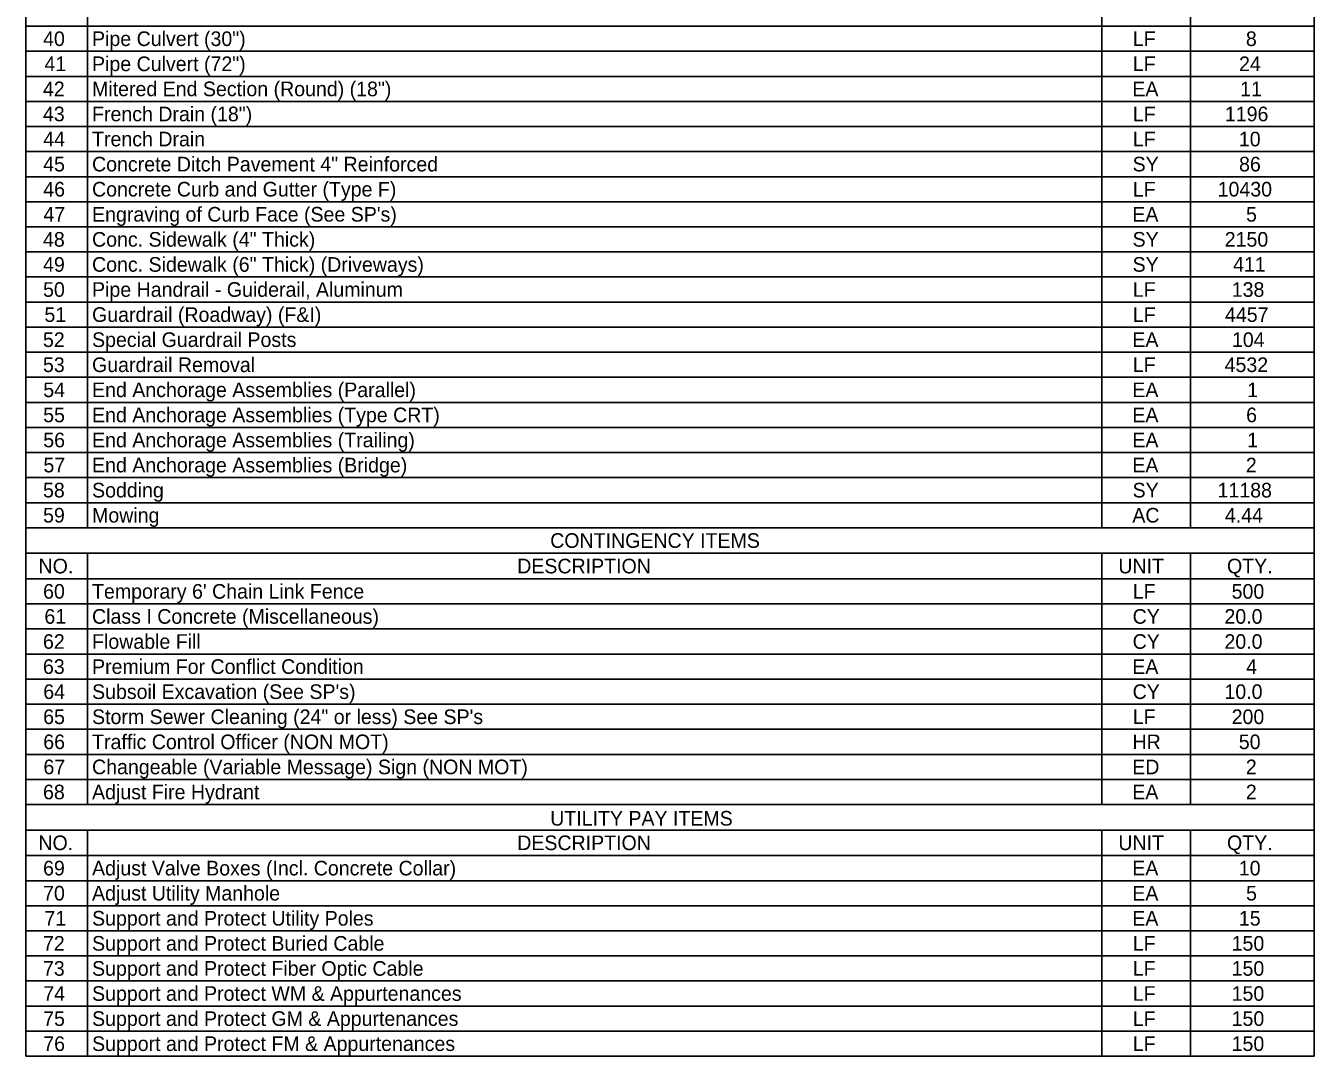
# Model space of a CAD drawing. Extents: x 0.3 to 14.6, y -0.2 to 9.6.
# Drawn here: x 0.29 to 6.07, y 0.33 to 4.95 of the extents above; entities that cross this region are included whole.
import ezdxf

# ---------------------------------------------------------------- set-up
doc = ezdxf.new("R2010")
doc.units = 0
for name, color, linetype in [('SumBoxBorder_dp', 7, 'Continuous'), ('SumBoxLines_dp', 7, 'Continuous'), ('TextLabel', 7, 'Continuous')]:
    doc.layers.add(name, color=color, linetype=linetype)

msp = doc.modelspace()

# ---------------------------------------------------------------- linework, layer by layer
at = {"layer": 'SumBoxBorder_dp'}
for p, q in [((0.2867, 9.5674), (0.2867, 0.3304)), ((6.0692, 9.5674), (6.0692, 0.3304)), ((0.2867, 2.7009), (6.0692, 2.7009)), ((0.2867, 2.5864), (6.0692, 2.5864)), ((0.2867, 2.5864), (6.0692, 2.5864)), ((0.2867, 1.4594), (6.0692, 1.4594)), ((0.2867, 1.3449), (6.0692, 1.3449)), ((0.2867, 1.3449), (6.0692, 1.3449)), ((0.2867, 0.3304), (6.0692, 0.3304))]:
    msp.add_line(p, q, dxfattribs=at)
at = {"layer": 'SumBoxLines_dp'}
for p, q in [((0.5642, 9.4529), (0.5642, 2.7009)), ((0.5642, 9.4529), (0.5642, 2.7009)), ((5.1167, 9.4529), (5.1167, 2.7009)), ((5.1167, 9.4529), (5.1167, 2.7009)), ((5.5142, 9.4529), (5.5142, 2.7009)), ((5.5142, 9.4529), (5.5142, 2.7009)), ((0.2867, 4.9509), (6.0692, 4.9509)), ((0.2867, 4.9509), (6.0692, 4.9509)), ((0.2867, 4.8384), (6.0692, 4.8384)), ((0.2867, 4.8384), (6.0692, 4.8384)), ((0.2867, 4.7259), (6.0692, 4.7259)), ((0.2867, 4.7259), (6.0692, 4.7259)), ((0.2867, 4.6134), (6.0692, 4.6134)), ((0.2867, 4.6134), (6.0692, 4.6134)), ((0.2867, 4.5009), (6.0692, 4.5009)), ((0.2867, 4.5009), (6.0692, 4.5009)), ((0.2867, 4.3884), (6.0692, 4.3884)), ((0.2867, 4.3884), (6.0692, 4.3884)), ((0.2867, 4.2759), (6.0692, 4.2759)), ((0.2867, 4.2759), (6.0692, 4.2759)), ((0.2867, 4.1634), (6.0692, 4.1634)), ((0.2867, 4.1634), (6.0692, 4.1634)), ((0.2867, 4.0509), (0.5642, 4.0509)), ((0.2867, 4.0509), (6.0692, 4.0509)), ((0.2867, 3.9384), (6.0692, 3.9384)), ((0.2867, 3.9384), (6.0692, 3.9384)), ((0.2867, 3.8259), (6.0692, 3.8259)), ((0.2867, 3.8259), (6.0692, 3.8259)), ((0.2867, 3.7134), (6.0692, 3.7134)), ((0.2867, 3.7134), (6.0692, 3.7134)), ((0.2867, 3.6009), (6.0692, 3.6009)), ((0.2867, 3.6009), (6.0692, 3.6009)), ((0.2867, 3.4884), (6.0692, 3.4884)), ((0.2867, 3.4884), (6.0692, 3.4884)), ((0.2867, 3.3759), (6.0692, 3.3759)), ((0.2867, 3.3759), (6.0692, 3.3759)), ((0.2867, 3.2634), (6.0692, 3.2634)), ((0.2867, 3.2634), (6.0692, 3.2634)), ((0.2867, 3.1509), (6.0692, 3.1509)), ((0.2867, 3.1509), (6.0692, 3.1509)), ((0.2867, 3.0384), (6.0692, 3.0384)), ((0.2867, 3.0384), (6.0692, 3.0384)), ((0.2867, 2.9259), (6.0692, 2.9259)), ((0.2867, 2.9259), (6.0692, 2.9259)), ((0.2867, 2.8134), (6.0692, 2.8134)), ((0.2867, 2.8134), (6.0692, 2.8134)), ((0.2867, 2.7009), (0.5642, 2.7009)), ((0.5642, 2.5864), (0.5642, 1.4594)), ((0.5642, 2.5864), (0.5642, 1.4594)), ((5.1167, 2.5864), (5.1167, 1.4594)), ((5.1167, 2.5864), (5.1167, 1.4594)), ((5.5142, 2.5864), (5.5142, 1.4594)), ((5.5142, 2.5864), (5.5142, 1.4594)), ((0.2867, 2.4719), (6.0692, 2.4719)), ((0.2867, 2.4719), (6.0692, 2.4719)), ((0.2867, 2.3594), (6.0692, 2.3594)), ((0.2867, 2.3594), (6.0692, 2.3594)), ((0.2867, 2.2469), (6.0692, 2.2469)), ((0.2867, 2.2469), (6.0692, 2.2469)), ((0.2867, 2.1344), (6.0692, 2.1344)), ((0.2867, 2.1344), (6.0692, 2.1344)), ((0.2867, 2.0219), (6.0692, 2.0219)), ((0.2867, 2.0219), (6.0692, 2.0219)), ((0.2867, 1.9094), (6.0692, 1.9094)), ((0.2867, 1.9094), (6.0692, 1.9094)), ((0.2867, 1.7969), (6.0692, 1.7969)), ((0.2867, 1.7969), (6.0692, 1.7969)), ((0.2867, 1.6844), (6.0692, 1.6844)), ((0.2867, 1.6844), (6.0692, 1.6844)), ((0.2867, 1.5719), (6.0692, 1.5719)), ((0.2867, 1.5719), (6.0692, 1.5719)), ((0.2867, 1.4594), (6.0692, 1.4594)), ((0.5642, 1.3449), (0.5642, 0.3304)), ((0.5642, 1.3449), (0.5642, 0.3304)), ((5.1167, 1.3449), (5.1167, 0.3304)), ((5.1167, 1.3449), (5.1167, 0.3304)), ((5.5142, 1.3449), (5.5142, 0.3304)), ((5.5142, 1.3449), (5.5142, 0.3304)), ((0.2867, 1.2304), (6.0692, 1.2304)), ((0.2867, 1.2304), (6.0692, 1.2304)), ((0.2867, 1.1179), (6.0692, 1.1179)), ((0.2867, 1.1179), (6.0692, 1.1179)), ((0.2867, 1.0054), (6.0692, 1.0054)), ((0.2867, 1.0054), (6.0692, 1.0054)), ((0.2867, 0.8929), (6.0692, 0.8929)), ((0.2867, 0.8929), (6.0692, 0.8929)), ((0.2867, 0.7804), (6.0692, 0.7804)), ((0.2867, 0.7804), (6.0692, 0.7804)), ((0.2867, 0.6679), (6.0692, 0.6679)), ((0.2867, 0.6679), (6.0692, 0.6679)), ((0.2867, 0.5554), (6.0692, 0.5554)), ((0.2867, 0.5554), (6.0692, 0.5554)), ((0.2867, 0.4429), (6.0692, 0.4429)), ((0.2867, 0.4429), (6.0692, 0.4429))]:
    msp.add_line(p, q, dxfattribs=at)

# ---------------------------------------------------------------- texts
at = {"layer": 'TextLabel'}
for s, height, p in [('40', 0.06563, (0.3644, 4.8619)), ('Pipe Culvert (30")', 0.065625, (0.5842, 4.8619)), ('LF', 0.06563, (5.255, 4.8619)), ('8', 0.0656, (5.7625, 4.8619)), ('41', 0.06563, (0.3704, 4.7494)), ('Pipe Culvert (72")', 0.065625, (0.5842, 4.7494)), ('LF', 0.06563, (5.255, 4.7494)), ('24', 0.06563, (5.7318, 4.7494)), ('42', 0.06563, (0.3639, 4.6369)), ('Mitered End Section (Round) (18")', 0.065625, (0.5842, 4.6369)), ('EA', 0.06563, (5.2529, 4.6369)), ('11', 0.06563, (5.7368, 4.6369)), ('43', 0.06563, (0.3639, 4.5244)), ('French Drain (18")', 0.065625, (0.5842, 4.5244)), ('LF', 0.06563, (5.255, 4.5244)), ('1196', 0.06563, (5.6683, 4.5244)), ('44', 0.06563, (0.3653, 4.4119)), ('Trench Drain', 0.065625, (0.5842, 4.4119)), ('LF', 0.06563, (5.255, 4.4119)), ('10', 0.06563, (5.731, 4.4119)), ('45', 0.06563, (0.3648, 4.2994)), ('Concrete Ditch Pavement 4" Reinforced', 0.065625, (0.5842, 4.2994)), ('SY', 0.06563, (5.2541, 4.2994)), ('86', 0.06563, (5.7318, 4.2994)), ('46', 0.06563, (0.3652, 4.1869)), ('Concrete Curb and Gutter (Type F)', 0.065625, (0.5842, 4.1869)), ('LF', 0.06563, (5.255, 4.1869)), ('10430', 0.06563, (5.6358, 4.1869)), ('47', 0.06563, (0.366, 4.0744)), ("Engraving of Curb Face (See SP's)", 0.065625, (0.5842, 4.0744)), ('EA', 0.06563, (5.2529, 4.0744)), ('5', 0.0656, (5.7631, 4.0744)), ('48', 0.06563, (0.3641, 3.9619)), ('Conc. Sidewalk (4" Thick)', 0.065625, (0.5842, 3.9619)), ('SY', 0.06563, (5.2541, 3.9619)), ('2150', 0.06563, (5.6675, 3.9619)), ('49', 0.06563, (0.3643, 3.8494)), ('Conc. Sidewalk (6" Thick) (Driveways)', 0.065625, (0.5842, 3.8494)), ('SY', 0.06563, (5.2541, 3.8494)), ('411', 0.06563, (5.7051, 3.8494)), ('50', 0.06563, (0.3644, 3.7369)), ('Pipe Handrail - Guiderail, Aluminum', 0.065625, (0.5842, 3.7369)), ('LF', 0.06563, (5.255, 3.7369)), ('138', 0.06563, (5.699, 3.7369)), ('51', 0.06563, (0.3704, 3.6244)), ('Guardrail (Roadway) (F&I)', 0.065625, (0.5842, 3.6244)), ('LF', 0.06563, (5.255, 3.6244)), ('4457', 0.06563, (5.6688, 3.6244)), ('52', 0.06563, (0.3639, 3.5119)), ('Special Guardrail Posts', 0.065625, (0.5842, 3.5119)), ('EA', 0.06563, (5.2529, 3.5119)), ('104', 0.06563, (5.7, 3.5119)), ('53', 0.06563, (0.3639, 3.3994)), ('Guardrail Removal', 0.065625, (0.5842, 3.3994)), ('LF', 0.06563, (5.255, 3.3994)), ('4532', 0.06563, (5.667, 3.3994)), ('End Anchorage Assemblies (Parallel)', 0.065625, (0.5842, 3.2869)), ('54', 0.06563, (0.3653, 3.2869)), ('EA', 0.06563, (5.2529, 3.2869)), ('1', 0.0656, (5.7686, 3.2869)), ('55', 0.06563, (0.3648, 3.1744)), ('End Anchorage Assemblies (Type CRT)', 0.065625, (0.5842, 3.1744)), ('EA', 0.06563, (5.2529, 3.1744)), ('6', 0.0656, (5.7636, 3.1744)), ('56', 0.06563, (0.3652, 3.0619)), ('End Anchorage Assemblies (Trailing)', 0.065625, (0.5842, 3.0619)), ('EA', 0.06563, (5.2529, 3.0619)), ('1', 0.0656, (5.7686, 3.0619)), ('57', 0.06563, (0.366, 2.9494)), ('End Anchorage Assemblies (Bridge)', 0.065625, (0.5842, 2.9494)), ('EA', 0.06563, (5.2529, 2.9494)), ('2', 0.0656, (5.7623, 2.9494)), ('58', 0.06563, (0.3641, 2.8369)), ('Sodding', 0.06563, (0.5842, 2.8369)), ('SY', 0.06563, (5.2541, 2.8369)), ('11188', 0.06563, (5.6354, 2.8369)), ('59', 0.06563, (0.3643, 2.7244)), ('Mowing', 0.06563, (0.5842, 2.7244)), ('AC', 0.06563, (5.2529, 2.7244)), ('4.44', 0.06563, (5.6683, 2.7244)), ('CONTINGENCY ITEMS', 0.065625, (2.6403, 2.6109)), ('NO.', 0.06563, (0.344, 2.4964)), ('DESCRIPTION', 0.065625, (2.4923, 2.4964)), ('UNIT', 0.06563, (5.1901, 2.4964)), ('QTY.', 0.06563, (5.6778, 2.4964)), ('60', 0.06563, (0.3644, 2.3829)), ("Temporary 6' Chain Link Fence", 0.065625, (0.5842, 2.3829)), ('LF', 0.06563, (5.2547, 2.3829)), ('500', 0.06563, (5.6985, 2.3829)), ('61', 0.06563, (0.3704, 2.2704)), ('Class I Concrete (Miscellaneous)', 0.065625, (0.5842, 2.2704)), ('CY', 0.06563, (5.2542, 2.2704)), ('20.0', 0.06563, (5.6663, 2.2704)), ('62', 0.06563, (0.3639, 2.1579)), ('Flowable Fill', 0.065625, (0.5842, 2.1579)), ('CY', 0.06563, (5.2542, 2.1579)), ('20.0', 0.06563, (5.6663, 2.1579)), ('63', 0.06563, (0.3639, 2.0454)), ('Premium For Conflict Condition', 0.065625, (0.5842, 2.0454)), ('EA', 0.06563, (5.2527, 2.0454)), ('4', 0.0656, (5.7638, 2.0454)), ('64', 0.06563, (0.3653, 1.9329)), ("Subsoil Excavation (See SP's)", 0.065625, (0.5842, 1.9329)), ('CY', 0.06563, (5.2542, 1.9329)), ('10.0', 0.06563, (5.6663, 1.9329)), ('65', 0.06563, (0.3648, 1.8204)), ('Storm Sewer Cleaning (24" or less) See SP\'s', 0.065625, (0.5842, 1.8204)), ('LF', 0.06563, (5.2547, 1.8204)), ('200', 0.06563, (5.6985, 1.8204)), ('66', 0.06563, (0.3652, 1.7079)), ('Traffic Control Officer (NON MOT)', 0.065625, (0.5842, 1.7079)), ('HR', 0.06563, (5.2537, 1.7079)), ('50', 0.06563, (5.7307, 1.7079)), ('67', 0.06563, (0.366, 1.5954)), ('Changeable (Variable Message) Sign (NON MOT)', 0.065625, (0.5842, 1.5954)), ('ED', 0.06563, (5.2524, 1.5954)), ('2', 0.0656, (5.7624, 1.5954)), ('68', 0.06563, (0.3641, 1.4829)), ('Adjust Fire Hydrant', 0.065625, (0.5842, 1.4829)), ('EA', 0.06563, (5.2527, 1.4829)), ('2', 0.0656, (5.7624, 1.4829)), ('UTILITY PAY ITEMS', 0.065625, (2.6403, 1.3649)), ('NO.', 0.06563, (0.3433, 1.2549)), ('DESCRIPTION', 0.065625, (2.4923, 1.2549)), ('UNIT', 0.06563, (5.1901, 1.2549)), ('QTY.', 0.06563, (5.6778, 1.2549)), ('69', 0.06563, (0.3643, 1.1414)), ('Adjust Valve Boxes (Incl. Concrete Collar)', 0.065625, (0.5842, 1.1414)), ('EA', 0.06563, (5.2527, 1.1414)), ('10', 0.06563, (5.7307, 1.1414)), ('70', 0.06563, (0.3644, 1.0289)), ('Adjust Utility Manhole', 0.065625, (0.5842, 1.0289)), ('EA', 0.06563, (5.2527, 1.0289)), ('5', 0.0656, (5.7633, 1.0289)), ('Support and Protect Utility Poles', 0.065625, (0.5842, 0.9164)), ('71', 0.06563, (0.3704, 0.9164)), ('EA', 0.06563, (5.2527, 0.9164)), ('15', 0.06563, (5.7311, 0.9164)), ('72', 0.06563, (0.3639, 0.8039)), ('Support and Protect Buried Cable', 0.065625, (0.5842, 0.8039)), ('LF', 0.06563, (5.2547, 0.8039)), ('150', 0.06563, (5.6985, 0.8039)), ('73', 0.06563, (0.3639, 0.6914)), ('Support and Protect Fiber Optic Cable', 0.065625, (0.5842, 0.6914)), ('LF', 0.06563, (5.2547, 0.6914)), ('150', 0.06563, (5.6985, 0.6914)), ('74', 0.06563, (0.3653, 0.5789)), ('Support and Protect WM & Appurtenances', 0.065625, (0.5842, 0.5789)), ('LF', 0.06563, (5.2547, 0.5789)), ('150', 0.06563, (5.6985, 0.5789)), ('75', 0.06563, (0.3648, 0.4664)), ('Support and Protect GM & Appurtenances', 0.065625, (0.5842, 0.4664)), ('LF', 0.06563, (5.2547, 0.4664)), ('150', 0.06563, (5.6985, 0.4664)), ('76', 0.06563, (0.3652, 0.3539)), ('Support and Protect FM & Appurtenances', 0.065625, (0.5842, 0.3539)), ('LF', 0.06563, (5.2547, 0.3539)), ('150', 0.06563, (5.6985, 0.3539))]:
    msp.add_text(s, height=height, dxfattribs=at).set_placement(p)

doc.saveas('drawing.dxf')
